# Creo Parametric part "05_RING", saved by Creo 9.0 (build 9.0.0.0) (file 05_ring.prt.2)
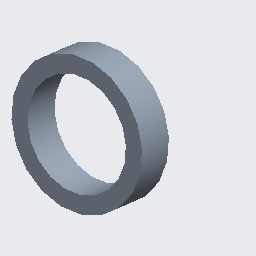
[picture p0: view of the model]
Units: millimeter Newton Second (mmNs); MM, TONNE, SECS

Created from: XX_MMNS_PART_SOLID_ABS.PRT

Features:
  1. datum plane "RIGHT"
  2. datum plane "TOP"
  3. datum plane "FRONT"
  4. coordinate system
  5. extrusion "Extrude 1"

Surfaces: 2 plane, 2 cylinder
